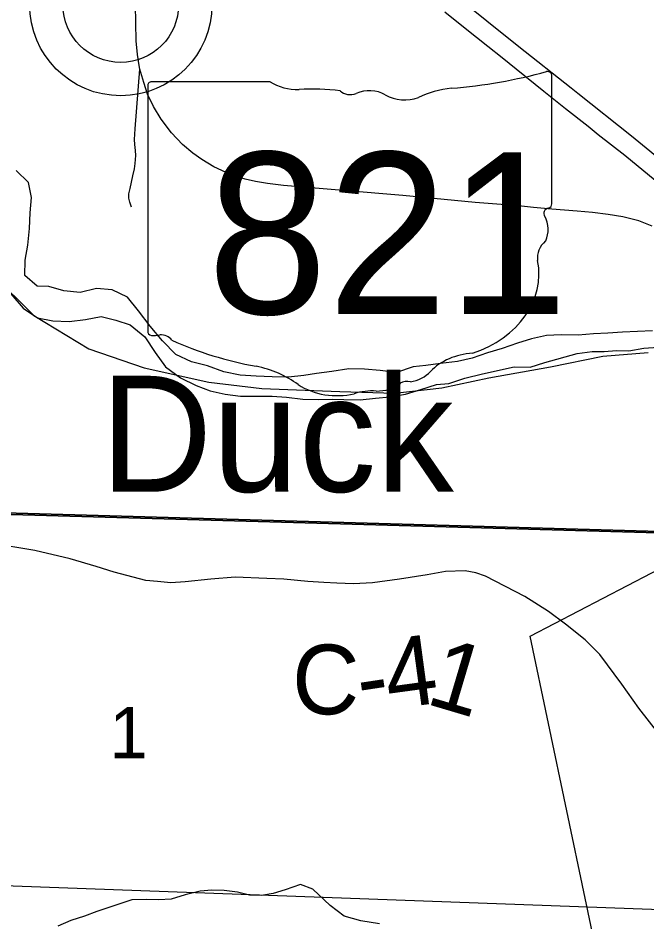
# Model space of a CAD drawing. Extents: x 0 to 34, y 0 to 22.
# Drawn here: x 3.957 to 4.47, y 18.326 to 19.064 of the extents above; entities that cross this region are included whole.
import ezdxf

# ---------------------------------------------------------------- set-up
doc = ezdxf.new("R2010")
doc.units = 0
for name, color, linetype in [('GM_X_City_Street', 7, 'Continuous'), ('GM_X_Corporation', 7, 'Continuous'), ('GM_X_County_Road', 7, 'Continuous'), ('GM_X_County_Road_Text', 7, 'Continuous'), ('GM_X_Interstate_Route', 7, 'Continuous'), ('GM_X_Major_River', 7, 'Continuous'), ('GM_X_Major_River_Text', 7, 'Continuous'), ('GM_X_Minor_River', 7, 'Continuous'), ('GM_X_Rail_Line', 7, 'Continuous'), ('GM_X_Section', 7, 'Continuous'), ('GM_X_Section_Text', 7, 'Continuous'), ('GM_X_State_Location', 7, 'Continuous'), ('GM_X_State_Route', 7, 'Continuous'), ('GM_X_State_Shield', 7, 'Continuous'), ('GM_X_Township_Road', 7, 'Continuous'), ('GM_X_Unincorporated', 7, 'Continuous')]:
    doc.layers.add(name, color=color, linetype=linetype)

msp = doc.modelspace()

# ---------------------------------------------------------------- linework, layer by layer
at = {"layer": 'GM_X_City_Street'}
msp.add_lwpolyline([(4.55035, 18.29077), (4.54634, 18.29395), (4.54411, 18.2964), (4.54303, 18.29892), (4.54202, 18.30302), (4.54253, 18.32326), (4.54381, 18.35045), (4.54421, 18.37383), (4.5433, 18.38745), (4.54198, 18.39497), (4.53993, 18.404), (4.53884, 18.40802), (4.53729, 18.41132), (4.53466, 18.41509), (4.52774, 18.42294), (4.52051, 18.43165), (4.48097, 18.47813), (4.46338, 18.5005), (4.44965, 18.52), (4.43175, 18.54427), (4.41974, 18.55616), (4.40368, 18.56903)], dxfattribs=at)
at = {"layer": 'GM_X_Corporation'}
msp.add_lwpolyline([(4.49036, 18.79443), (4.51525, 18.79819), (4.54005, 18.79578), (4.59414, 18.7656), (4.65471, 18.70558), (4.68751, 18.6156), (4.70475, 18.52409), (4.70401, 18.47963), (4.68515, 18.40014), (4.63403, 18.24423), (4.43455, 18.27418), (4.37475, 18.55924), (4.51371, 18.63148)], close=True, dxfattribs=at)
at = {"layer": 'GM_X_County_Road'}
msp.add_lwpolyline([(4.40368, 18.56903), (4.3897, 18.57945), (4.37033, 18.59171), (4.33834, 18.60826), (4.33049, 18.61096), (4.32166, 18.61255), (4.30573, 18.61194), (4.29065, 18.60936), (4.26809, 18.60569), (4.24627, 18.60274), (4.23058, 18.60201), (4.21709, 18.60238), (4.20655, 18.60299), (4.19331, 18.60397), (4.1737, 18.60569), (4.15984, 18.6063), (4.13422, 18.60728), (4.11412, 18.60569), (4.0934, 18.6036), (4.08163, 18.60287), (4.07075, 18.60372), (4.06107, 18.60465), (4.05093, 18.60725), (4.0353, 18.61153), (4.0207, 18.61609), (3.99958, 18.62242), (3.97074, 18.62912), (3.93409, 18.63516)], dxfattribs=at)
at = {"layer": 'GM_X_Interstate_Route'}
for points in [[(4.41365, 19.002), (4.40817, 19.00636), (4.36564, 19.04029), (4.31331, 19.08223), (4.26054, 19.12416), (4.22215, 19.15605), (4.20431, 19.17208), (4.19313, 19.18334), (4.17645, 19.20019), (4.16264, 19.21548), (4.14242, 19.2399), (4.12992, 19.25617), (4.11496, 19.27664), (4.09581, 19.30278), (4.08495, 19.31796), (4.05627, 19.35736), (4.04312, 19.37545), (4.01221, 19.41795), (3.98664, 19.45321), (3.97694, 19.46661), (3.95886, 19.49135), (3.93736, 19.52085)], [(4.47673, 18.93115), (4.45191, 18.95153), (4.43029, 18.96847), (4.42207, 18.97504), (4.40349, 18.98951), (4.38606, 19.00365), (4.36329, 19.02198), (4.35195, 19.03119), (4.34036, 19.04047), (4.32178, 19.05527), (4.30509, 19.06851)], [(4.48898, 18.9415), (4.45741, 18.96715), (4.41365, 19.002)]]:
    msp.add_lwpolyline(points, dxfattribs=at)
at = {"layer": 'GM_X_Major_River'}
for points in [[(4.12487, 18.77502), (4.11152, 18.7798), (4.09858, 18.78306), (4.0856, 18.78898), (4.07484, 18.80023), (4.06482, 18.81225), (4.05519, 18.82465), (4.04633, 18.83593), (4.03373, 18.84185), (4.02081, 18.84284), (4.00756, 18.83965), (3.99425, 18.84101), (3.98206, 18.84466), (3.97256, 18.84493), (3.96259, 18.85353), (3.96283, 18.86606), (3.96496, 18.87822), (3.96633, 18.89189), (3.96694, 18.90479), (3.96793, 18.91732), (3.96551, 18.92943), (3.95553, 18.93918)], [(3.951, 18.8386), (3.961, 18.82696), (3.97286, 18.81914), (3.98542, 18.81663), (3.99872, 18.81603), (4.01199, 18.8177), (4.02487, 18.82013), (4.03667, 18.81723), (4.04849, 18.8132), (4.06037, 18.80347), (4.06887, 18.79067), (4.07736, 18.77902), (4.08961, 18.77006), (4.10222, 18.76376), (4.11366, 18.75934), (4.12584, 18.75683), (4.13839, 18.75508), (4.15053, 18.75522), (4.16421, 18.755), (4.17599, 18.75438), (4.18929, 18.75264), (4.20182, 18.75241), (4.21321, 18.75254), (4.22271, 18.75228), (4.236, 18.75205), (4.24852, 18.75334), (4.26027, 18.75461), (4.27316, 18.75666), (4.28564, 18.7606), (4.2985, 18.76455), (4.30837, 18.76542), (4.3216, 18.76975), (4.33599, 18.77333), (4.36174, 18.77894), (4.37466, 18.77872), (4.38676, 18.78265), (4.41325, 18.78979), (4.42538, 18.79145), (4.43526, 18.79157), (4.44512, 18.79244), (4.45537, 18.79218), (4.4675, 18.79422), (4.47926, 18.79512)], [(4.47455, 18.80834), (4.45026, 18.8073), (4.43812, 18.80639), (4.42636, 18.80588), (4.41384, 18.80497), (4.40017, 18.80519), (4.38803, 18.80467), (4.37591, 18.80187), (4.36456, 18.79832), (4.35208, 18.794), (4.33997, 18.79045), (4.32749, 18.78613), (4.31537, 18.78333), (4.30172, 18.78165), (4.28959, 18.77999), (4.27935, 18.77911), (4.26574, 18.7744), (4.25243, 18.77614), (4.23951, 18.77713), (4.22697, 18.77736), (4.21295, 18.7753), (4.20044, 18.77363), (4.19021, 18.772), (4.17769, 18.77071), (4.1644, 18.77094), (4.15111, 18.77154), (4.13819, 18.77214), (4.12487, 18.77502)]]:
    msp.add_lwpolyline(points, dxfattribs=at)
at = {"layer": 'GM_X_Minor_River'}
msp.add_lwpolyline([(4.25184, 18.32439), (4.23664, 18.32695), (4.22295, 18.33065), (4.2115, 18.3393), (4.19736, 18.35286), (4.18746, 18.35659), (4.17496, 18.35234), (4.16511, 18.34924), (4.15563, 18.34766), (4.14575, 18.34797), (4.13587, 18.35018), (4.12523, 18.35163), (4.11497, 18.35194), (4.10549, 18.35112), (4.09335, 18.34801), (4.08199, 18.34452), (4.07174, 18.34407), (4.06149, 18.34439), (4.04972, 18.34393), (4.03987, 18.34083), (4.0213, 18.33464), (4.01108, 18.33078), (4.00009, 18.3273), (3.98949, 18.32268)], dxfattribs=at)
at = {"layer": 'GM_X_Rail_Line'}
for points in [[(4.58738, 20.9), (2.1, 20.9), (2.1, 18.71713), (2.78636, 18.69941), (2.78923, 18.69931), (2.92215, 18.69458), (2.92344, 18.69454), (3.84422, 18.66154), (3.84563, 18.6615), (4.54616, 18.6416), (4.5515, 18.76211), (4.55193, 18.77102), (4.5566, 18.86833), (4.55686, 18.87375), (4.55692, 18.87483), (4.55709, 18.88749), (4.57723, 20.31357), (4.57726, 20.31487)], [(2.1, 18.71713), (2.1, 14.1), (4.57815, 14.1), (4.56583, 14.96676), (4.55091, 15.53313), (4.54775, 16.58199), (4.54895, 17.6578), (4.5474, 17.7028), (4.54289, 17.94041), (4.5419, 17.96843), (4.54019, 18.28511), (4.54085, 18.37625), (4.53968, 18.39608), (4.53972, 18.40453), (4.53993, 18.44244), (4.54028, 18.5054), (4.54616, 18.6416), (3.84563, 18.6615), (3.84422, 18.66154), (2.92344, 18.69454), (2.92215, 18.69458), (2.78923, 18.69931), (2.78636, 18.69941)]]:
    msp.add_lwpolyline(points, close=True, dxfattribs=at)
msp.add_lwpolyline([(3.93557, 18.85454), (3.96983, 18.82085), (4.01466, 18.79362), (4.05996, 18.77834), (4.11253, 18.7665), (4.15592, 18.76142), (4.21949, 18.75881), (4.26445, 18.75748), (4.30283, 18.76191), (4.3412, 18.77003), (4.39139, 18.7789), (4.43419, 18.78776), (4.47109, 18.79071)], dxfattribs=at)
at = {"layer": 'GM_X_Section'}
for points in [[(4.56461, 19.68076), (4.56436, 19.63793), (4.54727, 18.64262), (3.55411, 18.6711), (3.56374, 19.72013)], [(3.55411, 18.6711), (4.54727, 18.64262), (4.54068, 18.33361), (3.55084, 18.36981)]]:
    msp.add_lwpolyline(points, close=True, dxfattribs=at)
at = {"layer": 'GM_X_State_Route'}
msp.add_lwpolyline([(4.47422, 18.89388), (4.46334, 18.8983), (4.45054, 18.90136), (4.43842, 18.90328), (4.42561, 18.90498), (4.41326, 18.906), (4.39242, 18.9077), (4.37746, 18.90895), (4.36523, 18.91031), (4.32999, 18.91314), (4.27085, 18.91881), (4.17353, 18.92708), (4.1605, 18.92866), (4.15075, 18.93025), (4.14226, 18.93218), (4.13489, 18.93433), (4.12685, 18.9375), (4.11677, 18.94226), (4.1068, 18.94826), (4.09966, 18.95348), (4.09116, 18.9605), (4.08221, 18.97002), (4.07383, 18.98123), (4.06748, 18.99143), (4.06266, 19.00166), (4.05944, 19.01099), (4.05638, 19.02186), (4.05587, 19.02497), (4.0544, 19.03389), (4.05343, 19.04516), (4.0528, 19.07445)], dxfattribs=at)
at = {"layer": 'GM_X_State_Shield'}
for p, q in [((4.39237, 18.91196), (4.39237, 19.01664)), ((4.16255, 19.01168), (4.06603, 19.01168)), ((4.06279, 19.00824), (4.06279, 18.80812)), ((4.39234, 18.91198), (4.39237, 18.91196))]:
    msp.add_line(p, q, dxfattribs=at)
for centre, major_axis, start_param, end_param in [((4.27497, 19.28452), (0.34952, 0), 4.814394, 5.042369), ((4.38871, 19.01708), (0.00367, 0), 6.141152, 7.989035), ((4.06656, 19.00867), (0.00382, 0), 1.712693, 3.28349), ((4.18554, 19.03492), (0.03703, 0), 4.042523, 4.731795), ((4.19782, 18.89933), (0.13295, 0), 1.404758, 1.657858), ((4.228, 19.0097), (0.01068, 0), 3.836095, 5.185415), ((4.24368, 18.98657), (0.02221, 0), 0.950623, 2.079405), ((4.31955, 18.95056), (0.07032, 0), 1.699011, 2.107814), ((4.27236, 19.0183), (0.02672, 0), 4.081561, 5.145723), ((4.39152, 18.90427), (0.00568, 0), 1.883978, 3.671073), ((4.38845, 18.91155), (0.00393, 0), 5.05454, 6.418171), ((4.3554, 18.89104), (0.03409, 0), 5.934695, 6.695948), ((4.40552, 18.86815), (0.0248, 0), 2.387724, 3.262537), ((4.29455, 18.85483), (0.08742, 0), 5.101752, 6.440018), ((4.0666, 18.80768), (0.00385, 0), 3.00124, 4.508301), ((4.06718, 18.82816), (0.0294, 0), 4.665946, 4.897461), ((4.07319, 18.79658), (0.0106, 0), 0.519207, 1.627899), ((4.20702, 18.97638), (0.2524, 0), 4.195997, 4.488961), ((4.33141, 18.75194), (0.04788, 0), 1.647645, 2.488434), ((4.13177, 18.71822), (0.07897, 0), 0.823519, 1.323587), ((4.27075, 18.78873), (0.02824, 0), 4.937069, 5.64225), ((4.2498, 18.7806), (0.0267, 0), 4.691044, 5.507374), ((4.27395, 18.76121), (0.00752, 0), 1.147584, 2.315152), ((4.21718, 18.79558), (0.05011, 0), 4.026481, 4.996735), ((4.24614, 18.72639), (0.04118, 0), 1.495662, 1.94098)]:
    msp.add_ellipse(centre, major_axis=major_axis, ratio=0.8, start_param=start_param, end_param=end_param, dxfattribs=at)
at = {"layer": 'GM_X_Township_Road'}
msp.add_lwpolyline([(4.04963, 18.90921), (4.04817, 18.91348), (4.04736, 18.91659), (4.04746, 18.92016), (4.04843, 18.92444), (4.05057, 18.935), (4.0519, 18.94066), (4.05261, 18.945), (4.05312, 18.95147), (4.05287, 18.95566), (4.0521, 18.96045), (4.05184, 18.96468), (4.05246, 18.97325), (4.05638, 19.02186)], dxfattribs=at)
at = {"layer": 'GM_X_Unincorporated'}
for radius in [0.0744, 0.04716]:
    msp.add_circle((4.04073, 19.07463), radius, dxfattribs=at)

# ---------------------------------------------------------------- texts
at = {"layer": 'GM_X_County_Road_Text'}
for s, rotation, p in [('4', 7.70399, (4.25986, 18.49935)), ('C', 359.09836, (4.18012, 18.49595)), ('1', 343.45628, (4.28825, 18.50453)), ('-', 8.57484, (4.23701, 18.49591))]:
    msp.add_text(s, height=0.05682, rotation=rotation, dxfattribs=at).set_placement(p)
at = {"layer": 'GM_X_Major_River_Text'}
msp.add_text('Duck', height=0.094693, rotation=0.00118, dxfattribs=at).set_placement((4.02399, 18.67706))
at = {"layer": 'GM_X_Section_Text'}
msp.add_text('1', height=0.04186, rotation=0.00001, dxfattribs=at).set_placement((4.0316, 18.45962))
at = {"layer": 'GM_X_State_Location'}
for s, p in [('r', (4.22387, 18.89488)), ('s', (4.22388, 18.89488))]:
    msp.add_text(s, height=0.000189, dxfattribs=at).set_placement(p)
msp.add_text('821', height=0.000189, rotation=0.00001, dxfattribs=at).set_placement((4.15702, 18.8811))
at = {"layer": 'GM_X_State_Shield'}
msp.add_text('821', height=0.131836, dxfattribs=at).set_placement((4.11135, 18.82223))

doc.saveas('drawing.dxf')
